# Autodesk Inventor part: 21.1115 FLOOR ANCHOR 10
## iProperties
Created: 2007-04
Part Number: 21.1115 FLOOR ANCHOR 10
Material: Steel
Document SubType Name: Modeling
Designer: Andy Moles
Density: 7.85 g/cm^3
Author: Andy Moles
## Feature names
1. Extrusion1
2. Extrusion2
3. Extrusion3
4. Extrusion4
5. Extrusion5
6. Extrusion6
7. Extrusion7
8. Revolution1
9. Fillet1
10. Chamfer1
